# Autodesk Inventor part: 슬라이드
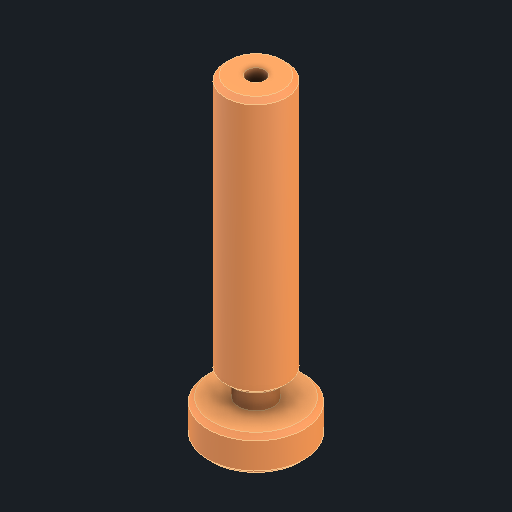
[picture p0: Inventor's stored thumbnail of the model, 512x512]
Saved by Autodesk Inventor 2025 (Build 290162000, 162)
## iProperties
Created: 2025-08
Part Number: 슬라이드
Material: 강철, 연강
Document SubType Name: Modeling
Designer: infra006
Density: 7.86 g/cm^3
Appearance: 기본값
Author: jhkim
Sending System: Autodesk Inventor 2026
Preprocessor: ST-DEVELOPER v20.1
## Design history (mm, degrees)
feature "솔리드1"
node "솔리드2"
